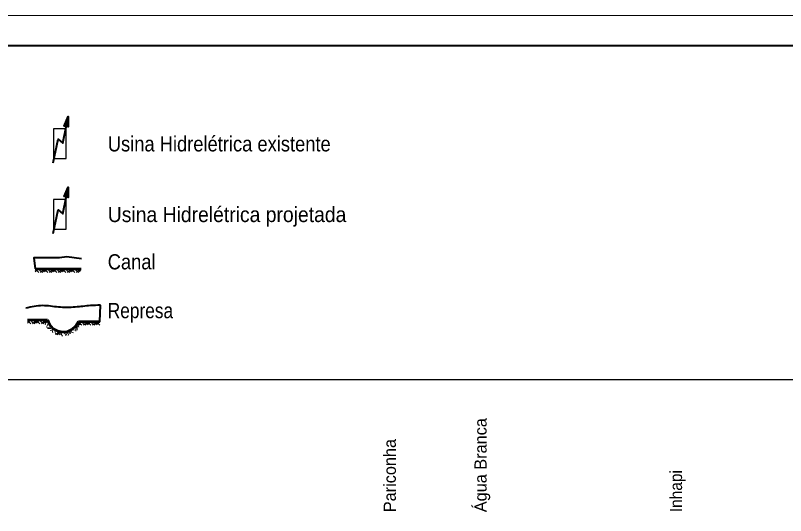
# Model space of a CAD drawing. Extents: x 8458 to 9360, y 19921 to 20366.
# Drawn here: x 8576.8 to 8766.6, y 20242.8 to 20366.2 of the extents above; entities that cross this region are included whole.
import ezdxf

# ---------------------------------------------------------------- set-up
doc = ezdxf.new("R2010")
doc.units = 0
doc.header["$LTSCALE"] = 1.2
doc.layers.add('1', color=7, linetype='Continuous', lineweight=40)
doc.layers.add('5', color=7, linetype='Continuous', lineweight=13)

msp = doc.modelspace()

# ---------------------------------------------------------------- linework, layer by layer
at = {"layer": '1', "lineweight": 13}
msp.add_lwpolyline([(8457.77, 19920.67), (9360.07, 19920.67), (9360.07, 20366.17), (8457.77, 20366.17)], close=True, dxfattribs=at)
at = {"layer": '1'}
msp.add_lwpolyline([(9352.57, 20358.67), (8495.27, 20358.67), (8495.27, 19928.17)], dxfattribs=at)
at = {"layer": '5', "lineweight": 53}
for p, q in [((8581.73, 20303.69), (8593.01, 20303.69)), ((8579.78, 20291.07), (8584.7, 20291.07)), ((8592.35, 20290.7), (8597.66, 20290.7))]:
    msp.add_line(p, q, dxfattribs=at)
at = {"layer": '5'}
for p, q in [((8582.14, 20303.69), (8581.73, 20303.29)), ((8582.54, 20303.69), (8581.73, 20302.89)), ((8582.08, 20303.23), (8582.59, 20302.73)), ((8582.48, 20303.64), (8583.19, 20302.93)), ((8583.96, 20303.69), (8582.99, 20302.73)), ((8583.23, 20303.69), (8583.6, 20303.33)), ((8583.96, 20303.29), (8583.39, 20302.73)), ((8584.36, 20303.69), (8583.96, 20303.29)), ((8584.76, 20303.69), (8583.96, 20302.89)), ((8584.3, 20303.23), (8584.81, 20302.73)), ((8584.71, 20303.64), (8585.42, 20302.93)), ((8586.18, 20303.69), (8585.21, 20302.73)), ((8585.46, 20303.69), (8585.82, 20303.33)), ((8586.18, 20303.29), (8585.61, 20302.73)), ((8586.58, 20303.69), (8586.18, 20303.29)), ((8586.99, 20303.69), (8586.18, 20302.89)), ((8586.53, 20303.23), (8587.04, 20302.73)), ((8586.93, 20303.64), (8587.64, 20302.93)), ((8588.4, 20303.69), (8587.44, 20302.73)), ((8587.68, 20303.69), (8588.04, 20303.33)), ((8588.4, 20303.29), (8587.84, 20302.73)), ((8588.81, 20303.69), (8588.4, 20303.29)), ((8589.21, 20303.69), (8588.4, 20302.89)), ((8588.75, 20303.23), (8589.26, 20302.73)), ((8589.15, 20303.64), (8589.86, 20302.93)), ((8590.63, 20303.69), (8589.66, 20302.73)), ((8589.91, 20303.69), (8590.27, 20303.33)), ((8590.63, 20303.29), (8590.06, 20302.73)), ((8591.03, 20303.69), (8590.63, 20303.29)), ((8591.43, 20303.69), (8590.63, 20302.89)), ((8590.97, 20303.23), (8591.48, 20302.73)), ((8591.38, 20303.64), (8592.09, 20302.93)), ((8592.85, 20303.69), (8591.88, 20302.73)), ((8592.13, 20303.69), (8592.49, 20303.33)), ((8592.85, 20303.29), (8592.29, 20302.73)), ((8580.19, 20291.07), (8579.78, 20290.66)), ((8580.59, 20291.07), (8579.78, 20290.26)), ((8580.13, 20290.61), (8580.64, 20290.1)), ((8580.53, 20291.01), (8581.24, 20290.3)), ((8582.01, 20291.07), (8581.04, 20290.1)), ((8581.28, 20291.07), (8581.65, 20290.71)), ((8582.01, 20290.66), (8581.44, 20290.1)), ((8582.41, 20291.07), (8582.01, 20290.66)), ((8582.81, 20291.07), (8582.01, 20290.26)), ((8582.35, 20290.61), (8582.86, 20290.1)), ((8582.76, 20291.01), (8583.47, 20290.3)), ((8584.23, 20291.07), (8583.26, 20290.1)), ((8583.51, 20291.07), (8583.87, 20290.71)), ((8584.23, 20290.66), (8583.66, 20290.1)), ((8585.03, 20290.33), (8583.97, 20290.74)), ((8584.43, 20290.56), (8584.17, 20289.89)), ((8584.63, 20291.07), (8584.23, 20290.66)), ((8585.04, 20291.07), (8584.23, 20290.26)), ((8584.87, 20290.7), (8584.33, 20290.9)), ((8585.86, 20289.2), (8584.5, 20289.27)), ((8584.96, 20290.36), (8584.6, 20289.42)), ((8585.38, 20289.74), (8585.35, 20289.23)), ((8591.77, 20289.66), (8591.72, 20288.29)), ((8591.96, 20290.01), (8592.11, 20289.47)), ((8592.05, 20289.36), (8592.01, 20288.56)), ((8592.16, 20290.37), (8592.46, 20289.27)), ((8592.18, 20290.29), (8593.14, 20290.56)), ((8592.33, 20289.74), (8593.03, 20289.94)), ((8592.75, 20290.7), (8592.35, 20290.3)), ((8593.15, 20290.7), (8592.35, 20289.9)), ((8592.7, 20290.24), (8593.2, 20289.74)), ((8593.1, 20290.65), (8593.81, 20289.94)), ((8594.57, 20290.7), (8593.6, 20289.74)), ((8593.85, 20290.7), (8594.21, 20290.34)), ((8594.57, 20290.3), (8594.01, 20289.74)), ((8594.97, 20290.7), (8594.57, 20290.3)), ((8595.38, 20290.7), (8594.57, 20289.9)), ((8594.92, 20290.24), (8595.43, 20289.74)), ((8595.32, 20290.65), (8596.03, 20289.94)), ((8596.79, 20290.7), (8595.83, 20289.74)), ((8596.07, 20290.7), (8596.43, 20290.34)), ((8596.79, 20290.3), (8596.23, 20289.74)), ((8597.2, 20290.7), (8596.79, 20290.3)), ((8597.6, 20290.7), (8596.79, 20289.9)), ((8597.14, 20290.24), (8597.65, 20289.74)), ((8585.57, 20288.93), (8584.77, 20288.97)), ((8586.5, 20288.73), (8585.4, 20288.43)), ((8585.88, 20288.56), (8586.07, 20287.86)), ((8586.43, 20288.71), (8586.69, 20287.74)), ((8587.81, 20288.22), (8586.67, 20287.47)), ((8587.73, 20287.83), (8587.06, 20287.39)), ((8587.1, 20288.37), (8587.38, 20287.94)), ((8588.6, 20288.06), (8587.65, 20287.43)), ((8588.2, 20288.14), (8587.73, 20287.83)), ((8588.06, 20287.7), (8588.45, 20287.1)), ((8588.55, 20288.06), (8589.34, 20287.44)), ((8590.01, 20288.28), (8589.16, 20287.21)), ((8589.29, 20288.2), (8589.69, 20287.88)), ((8590.15, 20288.02), (8589.87, 20287.27)), ((8590.35, 20288.55), (8590.15, 20288.02)), ((8590.71, 20288.72), (8590.32, 20287.65)), ((8590.49, 20288.11), (8591.16, 20287.86)), ((8590.73, 20288.62), (8591.73, 20288.58)), ((8591.24, 20289.17), (8591.75, 20289.15))]:
    msp.add_line(p, q, dxfattribs=at)
at = {"layer": '5', "lineweight": 40}
for p, q in [((8581.73, 20303.69), (8593.01, 20303.69)), ((8579.78, 20291.07), (8584.7, 20291.07))]:
    msp.add_line(p, q, dxfattribs=at)
at = {"layer": '5', "lineweight": 25}
msp.add_line((8509.89, 20276.38), (9341.84, 20276.38), dxfattribs=at)
at = {"layer": '5', "lineweight": 40}
for points in [[(8589.82, 20338.69), (8588.84, 20338.89), (8589.83, 20341.24), (8589.82, 20338.69), (8589.7, 20338.87), (8589.68, 20340.51), (8589.01, 20339.01), (8589.55, 20338.9), (8589.54, 20339.82), (8589.24, 20339.12), (8589.39, 20339.09), (8589.47, 20339.48)], [(8586.14, 20329.81), (8587.38, 20335.64), (8588.53, 20334.68), (8589.32, 20338.68)], [(8589.82, 20321.27), (8588.84, 20321.47), (8589.83, 20323.82), (8589.82, 20321.27), (8589.7, 20321.45), (8589.68, 20323.09), (8589.01, 20321.59), (8589.55, 20321.48), (8589.54, 20322.4), (8589.24, 20321.7), (8589.39, 20321.67), (8589.47, 20322.06)], [(8586.14, 20312.39), (8587.38, 20318.22), (8588.53, 20317.26), (8589.32, 20321.26)], [(8593.14, 20306.12), (8589.51, 20306.61), (8587.69, 20306.37), (8584.07, 20306.37), (8581.35, 20306.37), (8581.73, 20303.69)], [(8592.35, 20290.7), (8597.66, 20290.7), (8597.79, 20294.71)]]:
    msp.add_lwpolyline(points, dxfattribs=at)
at = {"layer": '5', "lineweight": 25}
for points in [[(8589.37, 20338.22), (8586.24, 20338.22), (8586.24, 20330.9), (8589.37, 20330.9)], [(8589.37, 20320.8), (8586.24, 20320.8), (8586.24, 20313.48), (8589.37, 20313.48)]]:
    msp.add_lwpolyline(points, close=True, dxfattribs=at)
at = {"layer": '5', "lineweight": 35}
msp.add_lwpolyline([(8581.35, 20306.37), (8584.07, 20306.37), (8587.69, 20306.37), (8589.51, 20306.61), (8593.14, 20306.12)], dxfattribs=at)
at = {"layer": '5', "lineweight": 53}
msp.add_lwpolyline([(8584.7, 20291.07), (8585.22, 20289.91), (8586.07, 20288.98), (8587.17, 20288.35), (8588.41, 20288.1), (8589.66, 20288.24), (8590.81, 20288.77), (8591.74, 20289.62), (8592.35, 20290.7)], dxfattribs=at)
at = {"layer": '5', "lineweight": 40}
msp.add_arc((8588.59, 20292.12), 4.02, 195.0853, 339.4479, dxfattribs=at)
at = {"layer": '5', "lineweight": 35}
msp.add_spline([(8579.39, 20293.98), (8583.54, 20294.59), (8587.43, 20294.23), (8591.57, 20294.23), (8595.33, 20294.59), (8597.79, 20294.71)], degree=3, dxfattribs=at)
at = {"layer": '5', "lineweight": 40}
msp.add_spline([(8597.79, 20294.71), (8595.33, 20294.59), (8591.57, 20294.23), (8587.43, 20294.23), (8583.54, 20294.59), (8579.39, 20293.98)], degree=3, dxfattribs=at)

# ---------------------------------------------------------------- texts
at = {"layer": '5'}
for s, width, p in [('Usina Hidrelétrica existente', 0.9, (8599.6, 20332.62)), ('Usina Hidrelétrica projetada', 0.95, (8599.6, 20315.2)), ('Canal', 0.9, (8599.58, 20303.53)), ('Represa', 0.85, (8599.58, 20291.5))]:
    msp.add_text(s, height=3.75, dxfattribs=dict(at, width=width)).set_placement(p)
for s, p in [('Água Branca', (8692.95, 20243.65)), ('Pariconha', (8670.58, 20243.65))]:
    msp.add_text(s, height=3, rotation=90, dxfattribs=at).set_placement(p)
at = {"layer": '5', "width": 0.95}
msp.add_text('Inhapi', height=3, rotation=90, dxfattribs=at).set_placement((8741.11, 20243.65))

doc.saveas('drawing.dxf')
